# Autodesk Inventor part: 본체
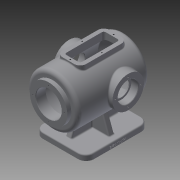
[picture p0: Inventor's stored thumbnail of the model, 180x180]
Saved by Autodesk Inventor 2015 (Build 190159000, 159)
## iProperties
Created: 2021-11
Part Number: 본체
Material: 일반
Document SubType Name: Modeling
Designer: G08
Density: 1 g/cm^3
Appearance: 기본값
Author: G08
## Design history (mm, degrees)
sketch "스케치1"
  geometry: L1 (65, -80)-(-65, -80); L2 (-65, -80)-(-65, 80); L3 (-65, 80)-(65, 80); L4 (65, 80)-(65, -80); L5 (65, -80)-(-65, 80); L6 (-65, -80)-(65, 80); 1 further point
  constraints: 12 end point, 2 midpoint, 2 parallel, 1 horizontal, 1 perpendicular
  dimensions: "d0" = 130 distance of L2.end L3.end; "d1" = 160 distance of L1.end L2.end
extrude "돌출1" new body sketch "스케치1" distance "d2" = 14; taper "d3" = 0 deg
sketch "스케치2"
  geometry: L1 (-65, 0)-(-65, 14) reference; L2 (-65, 14)-(65, 14) reference; L3 (65, 14)-(65, 0) reference; L4 (65, 0)-(-65, 0) reference; C1 r 65 at (0, 114); 1 further point
  constraints: 1 centre point
  dimensions: "d5" = 130 diameter of C1; "d6" = 114 distance from line of L4 C1.centre
extrude "돌출2" join sketch "스케치2" stored distance "d7" = 200; taper "d8" = 0 deg
sketch "스케치3"
  geometry: L1 (50, -7)-(-50, -7); L2 (-50, -7)-(-50, 7); L3 (-50, 7)-(50, 7); L4 (50, 7)-(50, -7); L5 (50, -7)-(-50, 7); L6 (-50, -7)-(50, 7); L7 (7, -60)-(-7, -60); L8 (-7, -60)-(-7, 60); L9 (-7, 60)-(7, 60); L10 (7, 60)-(7, -60); L11 (7, -60)-(-7, 60); L12 (-7, -60)-(7, 60); 1 further point
  constraints: 24 end point, 4 midpoint, 4 parallel, 2 horizontal, 2 perpendicular
  dimensions: "d9" = 14 distance of L8.end L9.end; "d10" = 14 distance of L3.end L1.start; "d11" = 120 distance of L9.end L7.start; "d12" = 100 distance of L2.end L3.end
extrude "돌출3" join sketch "스케치3" stored distance "d13" = 210; taper "d14" = 0 deg
sketch "스케치4"
  geometry: C1 r 65 at (0, 0) reference; C2 r 47.5 at (0, 0); 1 further point
  constraints: 1 centre point, 1 coincident
  dimensions: "d15" = 95 diameter of C2
extrude "돌출4" join sketch "스케치4" distance "d16" = 10; taper "d17" = 0 deg
sketch "스케치5"
  geometry: C1 r 47.5 at (0, 0) reference; 1 further point
hole "구멍1" sketch "스케치5" at (0, 0) diameter "d18" = 65; stored, may be unused: countersink angle "d22" = 90 deg, drill point angle "d24" = 0 deg; dims "d19" = 6, "d20" = 4, "d21" = 2, "d23" = 25
sketch "스케치6"
  geometry: C1 r 32.5 at (0, 0) reference; C2 r 55 at (0, 0); 1 further point
  constraints: 1 centre point, 1 coincident
  dimensions: "d25" = 110 diameter of C2
extrude "돌출5" cut sketch "스케치6" distance "d26" = 175; taper "d27" = 0 deg
sketch "스케치8"
  geometry: L1 (-80, 0)-(-80, 14) reference; L2 (-80, 14)-(-60, 14) reference; L3 (-60, 14)-(-60, 49) reference; L4 (-60, 49)-(-100, 49) reference; L5 (-100, 49)-(-100, 66.5) reference; L6 (-100, 66.5)-(-110, 66.5) reference; L7 (-110, 66.5)-(-110, 81.5) reference; L8 (-110, 81.5)-(-85, 81.5) reference; L9 (-85, 81.5)-(-85, 59) reference; L10 (-85, 59)-(90, 59) reference; L11 (90, 59)-(90, 169) reference; L12 (90, 169)-(-85, 169) reference; L13 (-85, 169)-(-85, 146.5) reference; L14 (-85, 146.5)-(-110, 146.5) reference; L15 (-110, 146.5)-(-110, 161.5) reference; L16 (-110, 161.5)-(-100, 161.5) reference; L17 (-100, 161.5)-(-100, 179) reference; L18 (-100, 179)-(100, 179) reference; L19 (100, 179)-(100, 49) reference; L20 (100, 49)-(60, 49) reference; L21 (60, 49)-(60, 14) reference; L22 (60, 14)-(80, 14) reference; L23 (80, 14)-(80, 0) reference; L24 (80, 0)-(-80, 0) reference; C1 r 21 at (17, 114); 1 further point
  constraints: 1 centre point
  dimensions: "d28" = 42 diameter of C1; "d29" = 127 distance from line of L15 C1.centre; "d30" = 114 distance from line of L24 C1.centre
extrude "돌출6" cut sketch "스케치8" stored distance "d31" = 175; taper "d32" = 0 deg
node "작업 평면3"
  node "작업 평면2"
sketch "스케치9"
  geometry: L1 (100, -65)-(100, 65) reference; L2 (-100, 65)-(-100, -65) reference; L3 (7, -41.533)-(-7, -41.533) reference; L4 (-7, -41.533)-(-7, -64.622) reference; L5 (-7, -64.622)-(-60, -64.622) reference; L6 (-60, -64.622)-(-60, -64.622) reference; L7 (-60, -64.622)-(-7, -64.622) reference; L8 (-7, -64.622)-(-7, -41.533) reference; L9 (-7, -41.533)-(7, -41.533) reference; L10 (7, -41.533)-(7, -64.622) reference; L11 (7, -64.622)-(60, -64.622) reference; L12 (60, -64.622)-(60, -64.622) reference; L13 (60, -64.622)-(7, -64.622) reference; L14 (7, -64.622)-(7, -41.533) reference; L15 (-80, -114)-(80, -114) reference; L16 (-80, -114)-(80, -114) reference; L17 (-80, -114)-(-80, -100) reference; L18 (80, -100)-(-80, -100) reference; L19 (80, -114)-(80, -100) reference; L20 (-110, 47.5)-(-110, -47.5) reference; C1 r 40 at (17, 0); 3 further points
  constraints: 1 centre point, 2 other
  dimensions: "d34" = 80 diameter of C1; "d35" = 114 distance from line of L15 C1.centre; "d36" = 127 distance from line of L20 C1.centre
extrude "돌출7" join sketch "스케치9" stored distance "d37" = 175; taper "d38" = 0 deg
sketch "스케치10"
  geometry: C1 r 40 at (0, 0) reference; C2 r 26 at (0, 0); 2 further points
  constraints: 1 centre point, 1 coincident, 1 other
  dimensions: "d39" = 52 diameter of C2
extrude "돌출8" cut sketch "스케치10" distance "d40" = 18; taper "d41" = 0 deg
node "작업 평면5"
  node "작업 평면4"
sketch "스케치11"
  geometry: L1 (-55, -85)-(-55, 90) reference; L2 (-65, -100)-(65, -100) reference; L3 (65, 100)-(-65, 100) reference; L4 (-47.5, -110)-(47.5, -110) reference; L5 (-65, -100)-(-65, 100) reference; L6 (65, -100)-(65, 100) reference; L7 (55, -85)-(55, 90) reference; L8 (30, -60)-(-30, -60); L9 (-30, -60)-(-30, 60); L10 (-30, 60)-(30, 60); L11 (30, 60)-(30, -60); L12 (30, -60)-(-30, 60); L13 (-30, -60)-(30, 60); L14 (75, 57)-(75, -23) reference; 2 further points
  constraints: 12 end point, 2 midpoint, 2 parallel, 1 horizontal, 1 perpendicular
  dimensions: "d43" = 60 distance of L9.end L10.end; "d44" = 120 distance of L8.end L9.end; "d45" = 50 distance between parallel lines of L4 L8; "d46" = 45 distance between parallel lines of L14 L11
extrude "돌출9" join sketch "스케치11" stored distance "d47" = 18; taper "d48" = 0 deg
sketch "스케치12"
  geometry: L1 (20, -50)-(-20, -50); L2 (-20, -50)-(-20, 50); L3 (-20, 50)-(20, 50); L4 (20, 50)-(20, -50); L5 (20, -50)-(-20, 50); L6 (-20, -50)-(20, 50); 1 further point
  constraints: 12 end point, 2 midpoint, 2 parallel, 1 horizontal, 1 perpendicular
  dimensions: "d49" = 40 distance of L2.end L3.end; "d50" = 100 distance of L1.end L2.end
extrude "돌출10" cut sketch "스케치12" distance "d51" = 30; taper "d52" = 0 deg
fillet "모깎기1" dims "d53" = 15
fillet "모깎기2" dims "d54" = 5
sketch "스케치13"
  geometry: 5 further points
  constraints: 2 horizontal alignment, 2 vertical alignment
  dimensions: "d55" = 25 distance of point (0, 0) point (-25, 0); "d56" = 50 distance of point (-25, 0) point (25, 0); "d57" = 110 distance of point (0, 55) point (0, -55); "d58" = 55 distance of point (0, 0) point (0, -55)
hole "구멍2" sketch "스케치13" at (-25, 0), (25, 0), (0, 55), (0, -55) diameter "d59" = 3.242; stored, may be unused: countersink angle "d63" = 90 deg, drill point angle "d65" = 118 deg; dims "d60" = 9, "d61" = 4, "d62" = 2, "d64" = 11
sketch "스케치14"
  geometry: L1 (0, 160)-(0, 0) reference; L2 (-31.658, 74.061)-(-31.658, 85.939); L3 (-31.658, 85.939)-(21.658, 85.939); L4 (21.658, 85.939)-(21.658, 74.061); L5 (21.658, 74.061)-(-31.658, 74.061); 2 further points
  constraints: 1 midpoint, 2 other
feature "엠보싱1" sketch "스케치14" dims "d68" = 0.5, "d69" = 0
sketch "스케치15"
  geometry: C1 r 26 at (0, 0) reference; 2 further points
  constraints: 1 horizontal alignment
  dimensions: "d70" = 32.5 distance of C1.centre point (-32.5, 0)
hole "구멍3" sketch "스케치15" at (-32.5, 0) diameter "d71" = 3.242; stored, may be unused: countersink angle "d75" = 90 deg, drill point angle "d77" = 118 deg; dims "d72" = 11, "d73" = 4, "d74" = 2, "d76" = 13
sketch "스케치16"
  geometry: C1 r 32.5 at (0, 0) reference; 2 further points
  constraints: 1 vertical alignment
  dimensions: "d81" = 40 distance of C1.centre point (0, 40)
hole "구멍4" sketch "스케치16" at (0, 40) diameter "d82" = 3.242; stored, may be unused: countersink angle "d86" = 90 deg, drill point angle "d88" = 118 deg; dims "d83" = 11, "d84" = 4, "d85" = 2, "d87" = 13
fillet "모깎기3" dims "d92" = 3
fillet "모깎기4" dims "d93" = 20
fillet "모깎기5" dims "d94" = 3
fillet "모깎기6" dims "d95" = 10
feature "면 기울기1" dims angle "d96" = 20 deg
feature "면 기울기2" dims angle "d97" = 20 deg
sketch "스케치18"
  geometry: C1 r 55 at (0, 0) reference; 1 further point
extrude "돌출11" join sketch "스케치18" distance "d100" = 20; taper "d101" = 0 deg
sketch "스케치17"
  geometry: L1 (-50, 184)-(-50, 169) reference; L2 (-50, 169)-(-85, 169) reference; L3 (-85, 81.5)-(-85, 59) reference; L4 (-110, 81.5)-(-85, 81.5) reference; L5 (-110, 146.5)-(-110, 152.379) reference; L6 (-110, 152.379)-(-97, 152.379) reference; L7 (-97, 152.379)-(-96.026, 154) reference; L8 (-96.026, 154)-(-97, 155.621) reference; L9 (-97, 155.621)-(-110, 155.621) reference; L10 (-110, 155.621)-(-110, 161.5) reference; L11 (-100, 66.5)-(-110, 66.5) reference; L12 (-100, 59)-(-100, 66.5) reference; L13 (-90, 179)-(-63, 179) reference; L14 (-60, 182)-(-60, 184) reference; L15 (-60, 184)-(-56.621, 184) reference; L16 (-56.621, 184)-(-56.621, 173) reference; L17 (-56.621, 173)-(-55, 172.026) reference; L18 (-55, 172.026)-(-53.379, 173) reference; L19 (-53.379, 173)-(-53.379, 184) reference; L20 (-53.379, 184)-(-50, 184) reference; L21 (70, 169)-(50, 169) reference; L22 (50, 169)-(50, 184) reference; L23 (50, 184)-(53.379, 184) reference; L24 (53.379, 184)-(53.379, 173) reference; L25 (53.379, 173)-(55, 172.026) reference; L26 (55, 172.026)-(56.621, 173) reference; L27 (56.621, 173)-(56.621, 184) reference; L28 (56.621, 184)-(60, 184) reference; L29 (60, 184)-(60, 182) reference; L30 (63, 179)-(100, 179) reference; L31 (100, 179)-(100, 49) reference; L32 (100, 49)-(47.261, 49) reference; L33 (47.261, 49)-(60, 14) reference; L34 (60, 14)-(77, 14) reference; L35 (80, 11)-(80, 0) reference; L36 (80, 0)-(-80, 0) reference; L37 (-80, 0)-(-80, 11) reference; L38 (-77, 14)-(-60, 14) reference; L39 (-60, 14)-(-47.261, 49) reference; L40 (-47.261, 49)-(-90, 49) reference; L41 (-100, 161.5)-(-100, 169) reference; L42 (-110, 161.5)-(-100, 161.5) reference; L43 (-110, 66.5)-(-110, 72.379) reference; L44 (-110, 72.379)-(-97, 72.379) reference; L45 (-97, 72.379)-(-96.026, 74) reference; L46 (-96.026, 74)-(-97, 75.621) reference; L47 (-97, 75.621)-(-110, 75.621) reference; L48 (-110, 75.621)-(-110, 81.5) reference; L49 (-85, 146.5)-(-110, 146.5) reference; L50 (-85, 169)-(-85, 146.5) reference; L51 (100, 49)-(100, 179) reference; L52 (100, 114)-(-110, 114); L53 (-85, 59)-(70, 59) reference; L54 (70, 59)-(70, 169) reference; A1 r 10 centre (-90, 59) between (-100, 59) and (-90, 49) reference; A2 r 3 centre (-63, 182) between (-63, 179) and (-60, 182) reference; A3 r 3 centre (63, 182) between (60, 182) and (63, 179) reference; A4 r 3 centre (77, 11) between (80, 11) and (77, 14) reference; A5 r 3 centre (-77, 11) between (-77, 14) and (-80, 11) reference; A6 r 10 centre (-90, 169) between (-90, 179) and (-100, 169) reference; A7 r 130.668 centre (0, 114) between (63.86, 0) and (79.982, 10.671); A8 r 100 centre (0, 114) between (100, 114) and (75.993, 179); 1 further point; 1 other entity
  constraints: 5 point on circle, 2 centre point, 2 end point, 2 point on line, 1 horizontal, 1 midpoint, 1 tangent, 2 other
  dimensions: "d99" = 100 radius of A8
revolve "회전1" sketch "스케치17" stored, may be unused: angle "d102" = 90 deg
sketch "스케치19"
  geometry: L1 (50, 169)-(50, 184) reference; L2 (50, 184)-(53.379, 184) reference; L3 (53.379, 184)-(53.379, 173) reference; L4 (53.379, 173)-(55, 172.026) reference; L5 (55, 172.026)-(56.621, 173) reference; L6 (56.621, 173)-(56.621, 184) reference; L7 (56.621, 184)-(60, 184) reference; L8 (60, 184)-(60, 182) reference; L9 (63, 179)-(75.993, 179) reference; L10 (75.993, 49)-(47.261, 49) reference; L11 (47.261, 49)-(60, 14) reference; L12 (60, 14)-(77, 14) reference; L13 (80, 11)-(80, 0) reference; L14 (80, 0)-(-80, 0) reference; L15 (-80, 0)-(-80, 11) reference; L16 (-77, 14)-(-60, 14) reference; L17 (-60, 14)-(-47.261, 49) reference; L18 (-47.261, 49)-(-90, 49) reference; L19 (-100, 59)-(-100, 66.5) reference; L20 (-100, 66.5)-(-110, 66.5) reference; L21 (-110, 66.5)-(-110, 72.379) reference; L22 (-110, 72.379)-(-97, 72.379) reference; L23 (-97, 72.379)-(-96.026, 74) reference; L24 (-96.026, 74)-(-97, 75.621) reference; L25 (-97, 75.621)-(-110, 75.621) reference; L26 (-110, 75.621)-(-110, 81.5) reference; L27 (-110, 81.5)-(-85, 81.5) reference; L28 (-85, 81.5)-(-85, 59) reference; L29 (-85, 59)-(70, 59) reference; L30 (70, 59)-(70, 169) reference; L31 (70, 169)-(50, 169) reference; L32 (-50, 184)-(-50, 169) reference; L33 (-50, 169)-(-85, 169) reference; L34 (-85, 169)-(-85, 146.5) reference; L35 (-85, 146.5)-(-110, 146.5) reference; L36 (-110, 146.5)-(-110, 152.379) reference; L37 (-110, 152.379)-(-97, 152.379) reference; L38 (-97, 152.379)-(-96.026, 154) reference; L39 (-96.026, 154)-(-97, 155.621) reference; L40 (-97, 155.621)-(-110, 155.621) reference; L41 (-110, 155.621)-(-110, 161.5) reference; L42 (-110, 161.5)-(-100, 161.5) reference; L43 (-100, 161.5)-(-100, 169) reference; L44 (-90, 179)-(-63, 179) reference; L45 (-60, 182)-(-60, 184) reference; L46 (-60, 184)-(-56.621, 184) reference; L47 (-56.621, 184)-(-56.621, 173) reference; L48 (-56.621, 173)-(-55, 172.026) reference; L49 (-55, 172.026)-(-53.379, 173) reference; L50 (-53.379, 173)-(-53.379, 184) reference; L51 (-53.379, 184)-(-50, 184) reference; L52 (0, 114)-(90, 114); L53 (45, 170.833)-(-45, 170.833) reference; L54 (0, 169)-(0, 114); L55 (71.239, 169)-(0, 169); A1 r 3 centre (63, 182) between (60, 182) and (63, 179) reference; A2 r 100 centre (0, 114) between (75.993, 49) and (75.993, 179) reference; A3 r 3 centre (77, 11) between (80, 11) and (77, 14) reference; A4 r 3 centre (-77, 11) between (-77, 14) and (-80, 11) reference; A5 r 10 centre (-90, 59) between (-100, 59) and (-90, 49) reference; A6 r 10 centre (-90, 169) between (-90, 179) and (-100, 169) reference; A7 r 3 centre (-63, 182) between (-63, 179) and (-60, 182) reference; A8 r 90 centre (0, 114) between (90, 114) and (71.239, 169); 3 further points
  constraints: 6 end point, 2 horizontal, 2 midpoint, 2 point on circle, 1 centre point, 1 point on line, 1 vertical
  dimensions: "d104" = 10 radial gap between concentric circles of A2 A8
revolve "회전2" sketch "스케치19" stored, may be unused: angle "d105" = 90 deg
fillet "모깎기7" dims "d106" = 10
fillet "모깎기8" dims "d107" = 3
fillet "모깎기9" dims "d108" = 3
chamfer "모따기1" distance "d109" = 1; stored, may be unused: second distance "d110" = 2, angle "d111" = 45 deg
fillet "모깎기10" dims "d112" = 3
fillet "모깎기11" dims "d113" = 3
node "솔리드1"
mirror "대칭1"
pattern_circular "원형 패턴1" dims angle "d79" = 360 deg
mirror "대칭2"
pattern_circular "원형 패턴2" dims angle "d90" = 360 deg
node "투영된 루프1"
node "투영된 루프2"
node "절단 모서리 투영1"
node "절단 모서리 투영2"
node "절단 모서리 투영3"
node "절단 모서리 투영4"
other parameters: "d42" = 5
